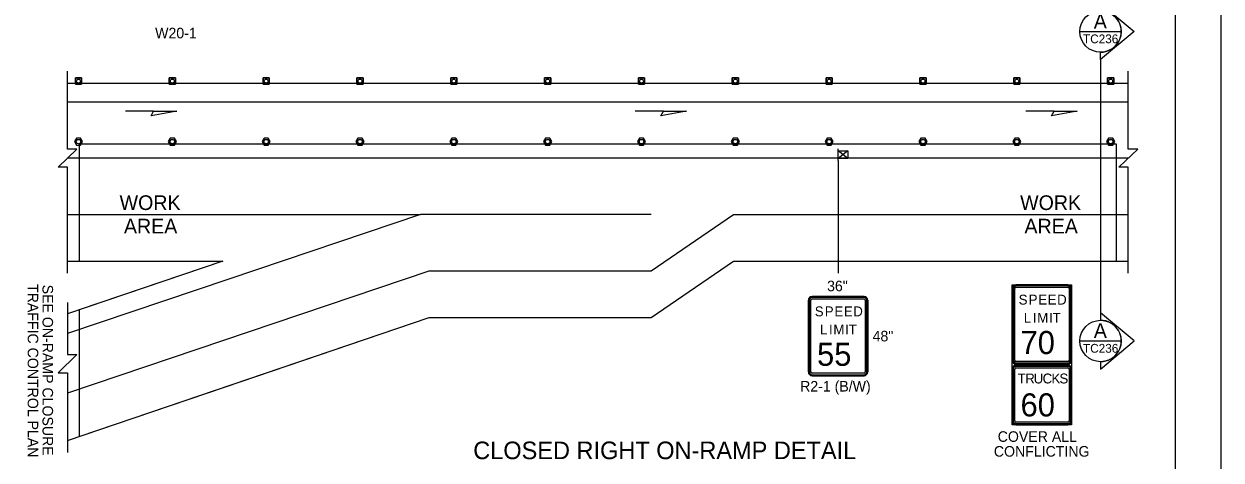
# Model space of a CAD drawing. Extents: x 99999 to 100116, y 99995 to 100013.
# Drawn here: x 100067.9 to 100076.06, y 100001.79 to 100004.77 of the extents above; entities that cross this region are included whole.
import ezdxf

# ---------------------------------------------------------------- set-up
doc = ezdxf.new("R2010")
doc.units = 0
for name, color, linetype in [('Default', 7, 'Continuous'), ('RD_MK_LineEdgeYellow', 7, 'Continuous'), ('RD_MK_LineLane', 7, 'Continuous'), ('SH_DE_DetailHeading2Text', 7, 'Continuous'), ('SH_GI_PlotLimits', 7, 'Continuous'), ('SH_GI_SheetBorder', 7, 'Continuous'), ('SH_TI_WZSectionCut', 7, 'Continuous'), ('TR_SN_ConstructionSigns', 7, 'Continuous'), ('TR_WZ_PortableSignMount5ftMinBlk-Wht', 7, 'Continuous'), ('TR_WZ_TallChanDevice', 7, 'Continuous'), ('TR_WZ_TrafficCone', 7, 'Continuous'), ('TR_WZ_WorkAreaLabel', 7, 'Continuous'), ('TR_WZ_WorkZoneDetails', 7, 'Continuous')]:
    doc.layers.add(name, color=color, linetype=linetype)

msp = doc.modelspace()

# ---------------------------------------------------------------- linework, layer by layer
at = {"layer": 'Default'}
for p, q in [((100074.638, 100002.4156), (100074.638, 100002.0613)), ((100075.0177, 100002.441), (100074.6633, 100002.441)), ((100075.043, 100002.0613), (100075.043, 100002.4156)), ((100074.6633, 100002.036), (100075.0177, 100002.036))]:
    msp.add_line(p, q, dxfattribs=at)
for centre, start, end in [((100074.6633, 100002.4156), 90, 180), ((100075.0177, 100002.4156), 0, 90), ((100074.6633, 100002.0613), 180, 270.00001), ((100075.0177, 100002.0613), 270.00001, 0.00001)]:
    msp.add_arc(centre, 0.0253, start, end, dxfattribs=at)
at = {"layer": 'RD_MK_LineEdgeYellow'}
for p, q in [((100068.195, 100004.238), (100075.43, 100004.238)), ((100068.195, 100003.47), (100069.2533, 100003.47)), ((100072.1758, 100003.086), (100072.7368, 100003.47)), ((100072.7368, 100003.47), (100075.43, 100003.47)), ((100070.6655, 100003.086), (100068.195, 100002.2517)), ((100070.6655, 100003.086), (100072.1758, 100003.086)), ((100069.2943, 100003.0282), (100068.195, 100002.657))]:
    msp.add_line(p, q, dxfattribs=at)
at = {"layer": 'RD_MK_LineLane'}
for points in [[(100075.43, 100003.854), (100068.195, 100003.854)], [(100072.1758, 100003.47), (100070.6024, 100003.47)]]:
    msp.add_lwpolyline(points, dxfattribs=at)
at = {"layer": 'SH_GI_PlotLimits'}
msp.add_lwpolyline([(100059.0625, 99999.6875), (100076.0625, 99999.6875), (100076.0625, 100010.6875), (100059.0625, 100010.6875)], close=True, dxfattribs=at)
at = {"layer": 'SH_GI_SheetBorder'}
msp.add_line((100075.75, 100010.375), (100075.75, 100000), dxfattribs=at)
at = {"layer": 'SH_TI_WZSectionCut'}
for p, q in [((100075.2407, 100004.9082), (100075.4688, 100004.7171)), ((100075.4688, 100004.7171), (100075.2407, 100004.526)), ((100075.2407, 100004.526), (100075.2407, 100004.5759)), ((100075.2407, 100004.526), (100075.2407, 100002.798)), ((100075.2407, 100002.798), (100075.2407, 100002.748)), ((100075.4689, 100002.6068), (100075.2407, 100002.798)), ((100075.2407, 100002.4157), (100075.4689, 100002.6068)), ((100075.2407, 100002.4656), (100075.2407, 100002.4157))]:
    msp.add_line(p, q, dxfattribs=at)
for points in [[(100075.0995, 100004.7171), (100075.3819, 100004.7171)], [(100075.0995, 100002.6068), (100075.3819, 100002.6068)]]:
    msp.add_lwpolyline(points, dxfattribs=at)
for centre in [(100075.2407, 100004.7171), (100075.2407, 100002.6068)]:
    msp.add_circle(centre, 0.1412, dxfattribs=at)
for centre in [(100075.2407, 100004.7171), (100075.2407, 100002.6068)]:
    msp.add_arc(centre, 0.1412, 269.99779, 90.00221, dxfattribs=at)
at = {"layer": 'TR_SN_ConstructionSigns'}
for p, q in [((100074.638, 100002.4753), (100074.638, 100002.9646)), ((100074.638, 100002.9646), (100074.638, 100002.4753)), ((100074.6451, 100002.9646), (100074.6451, 100002.4753)), ((100074.6549, 100002.4753), (100074.6549, 100002.9646)), ((100074.6633, 100002.99), (100075.0177, 100002.99)), ((100075.0177, 100002.99), (100074.6633, 100002.99)), ((100075.0177, 100002.9829), (100074.6633, 100002.9829)), ((100074.6633, 100002.9731), (100075.0177, 100002.9731)), ((100075.0261, 100002.9646), (100075.0261, 100002.4753)), ((100075.036, 100002.4753), (100075.036, 100002.9646)), ((100075.043, 100002.9646), (100075.043, 100002.4753)), ((100075.043, 100002.4753), (100075.043, 100002.9646)), ((100073.2475, 100002.3953), (100073.2475, 100002.8846)), ((100073.2475, 100002.8846), (100073.2475, 100002.3953)), ((100073.2546, 100002.8846), (100073.2546, 100002.3953)), ((100073.2644, 100002.3953), (100073.2644, 100002.8846)), ((100073.2728, 100002.91), (100073.6272, 100002.91)), ((100073.6272, 100002.91), (100073.2728, 100002.91)), ((100073.6272, 100002.9029), (100073.2728, 100002.9029)), ((100073.2728, 100002.8931), (100073.6272, 100002.8931)), ((100073.6357, 100002.8846), (100073.6357, 100002.3953)), ((100073.6455, 100002.3953), (100073.6455, 100002.8846)), ((100073.6525, 100002.8846), (100073.6525, 100002.3953)), ((100073.6525, 100002.3953), (100073.6525, 100002.8846)), ((100075.0177, 100002.4668), (100074.6633, 100002.4668)), ((100073.6272, 100002.3868), (100073.2728, 100002.3868)), ((100073.2728, 100002.377), (100073.6272, 100002.377)), ((100074.638, 100002.0613), (100074.638, 100002.4156)), ((100074.638, 100002.4156), (100074.638, 100002.0613)), ((100074.6451, 100002.4156), (100074.6451, 100002.0613)), ((100074.6549, 100002.0613), (100074.6549, 100002.4156)), ((100074.6633, 100002.457), (100075.0177, 100002.457)), ((100075.0177, 100002.45), (100074.6633, 100002.45)), ((100074.6633, 100002.45), (100075.0177, 100002.45)), ((100074.6633, 100002.441), (100075.0177, 100002.441)), ((100075.0177, 100002.441), (100074.6633, 100002.441)), ((100075.0177, 100002.4339), (100074.6633, 100002.4339)), ((100074.6633, 100002.4241), (100075.0177, 100002.4241)), ((100075.0261, 100002.4156), (100075.0261, 100002.0613)), ((100075.036, 100002.0613), (100075.036, 100002.4156)), ((100075.043, 100002.4156), (100075.043, 100002.0613)), ((100075.043, 100002.0613), (100075.043, 100002.4156)), ((100073.6272, 100002.37), (100073.2728, 100002.37)), ((100073.2728, 100002.37), (100073.6272, 100002.37)), ((100075.0177, 100002.0528), (100074.6633, 100002.0528)), ((100074.6633, 100002.043), (100075.0177, 100002.043)), ((100075.0177, 100002.036), (100074.6633, 100002.036)), ((100074.6633, 100002.036), (100075.0177, 100002.036))]:
    msp.add_line(p, q, dxfattribs=at)
msp.add_lwpolyline([(100074.638, 100002.99), (100075.043, 100002.99), (100075.043, 100002.036), (100074.638, 100002.036)], close=True, dxfattribs=at)
for centre, radius, start, end in [((100074.6633, 100002.9646), 0.0253, 90, 180), ((100074.6633, 100002.9646), 0.0253, 90, 180), ((100074.6633, 100002.9646), 0.0183, 90, 180), ((100074.6633, 100002.9646), 0.00844, 90, 180), ((100075.0177, 100002.9646), 0.0253, 0, 90), ((100075.0177, 100002.9646), 0.0253, 360, 90), ((100075.0177, 100002.9646), 0.0183, 0, 90), ((100075.0177, 100002.9646), 0.00844, 360, 90), ((100073.2728, 100002.8846), 0.0253, 90, 180), ((100073.2728, 100002.8846), 0.0253, 90, 180), ((100073.2728, 100002.8846), 0.0183, 90, 180), ((100073.2728, 100002.8846), 0.00844, 90, 180), ((100073.6272, 100002.8846), 0.0253, 360, 90), ((100073.6272, 100002.8846), 0.0253, 360, 90), ((100073.6272, 100002.8846), 0.0183, 0, 90), ((100073.6272, 100002.8846), 0.00844, 360, 90), ((100074.6633, 100002.4753), 0.0253, 180, 270), ((100074.6633, 100002.4753), 0.0253, 180, 270), ((100074.6633, 100002.4753), 0.0183, 180, 270), ((100074.6633, 100002.4753), 0.00844, 180, 270), ((100075.0177, 100002.4753), 0.0253, 270, 0), ((100075.0177, 100002.4753), 0.0183, 270, 360), ((100075.0177, 100002.4753), 0.00844, 270, 0), ((100075.0177, 100002.4753), 0.0253, 270, 0), ((100073.2728, 100002.3953), 0.0253, 180, 270), ((100073.2728, 100002.3953), 0.0253, 180, 270), ((100073.2728, 100002.3953), 0.0183, 180, 270), ((100073.2728, 100002.3953), 0.00844, 180, 270), ((100073.6272, 100002.3953), 0.0253, 270, 360), ((100073.6272, 100002.3953), 0.0183, 270, 360), ((100073.6272, 100002.3953), 0.00844, 270, 0), ((100073.6272, 100002.3953), 0.0253, 270, 360), ((100074.6633, 100002.4156), 0.0253, 90, 180), ((100074.6633, 100002.4156), 0.0253, 90, 180), ((100074.6633, 100002.4156), 0.0183, 90, 180), ((100074.6633, 100002.4156), 0.00844, 90, 180), ((100075.0177, 100002.4156), 0.0253, 0, 90), ((100075.0177, 100002.4156), 0.0253, 360, 90), ((100075.0177, 100002.4156), 0.0183, 0, 90), ((100075.0177, 100002.4156), 0.00844, 360, 90), ((100074.6633, 100002.0613), 0.0253, 180, 270), ((100074.6633, 100002.0613), 0.0253, 180, 270), ((100075.0177, 100002.0613), 0.0253, 270, 0), ((100075.0177, 100002.0613), 0.0253, 270, 0), ((100075.0177, 100002.0613), 0.0183, 270, 360), ((100075.0177, 100002.0613), 0.00844, 270, 0)]:
    msp.add_arc(centre, radius, start, end, dxfattribs=at)
for major_axis, ratio, start_param, end_param in [((-0.0183, 0), 0.999596, 0, 1.570796), ((0.00844, 0), 0.99908, 3.141593, 4.712389)]:
    msp.add_ellipse((100074.6633, 100002.0613), major_axis=major_axis, ratio=ratio, start_param=start_param, end_param=end_param, dxfattribs=at)
at = {"layer": 'TR_WZ_PortableSignMount5ftMinBlk-Wht'}
for p, q in [((100073.45, 100003.838), (100073.45, 100003.918)), ((100073.5167, 100003.904), (100073.45, 100003.852)), ((100073.5167, 100003.852), (100073.45, 100003.904)), ((100073.4834, 100003.878), (100073.4834, 100003.878)), ((100073.4835, 100003.878), (100073.4835, 100003.878))]:
    msp.add_line(p, q, dxfattribs=at)
msp.add_lwpolyline([(100073.5167, 100003.904), (100073.5167, 100003.852), (100073.45, 100003.852), (100073.45, 100003.904)], close=True, dxfattribs=at)
at = {"layer": 'TR_WZ_TallChanDevice'}
for points in [[(100068.2833, 100003.9909), (100068.2555, 100003.9909), (100068.2417, 100003.9669), (100068.2555, 100003.9429), (100068.2833, 100003.9429), (100068.2971, 100003.9669)], [(100068.9233, 100003.9909), (100068.8955, 100003.9909), (100068.8817, 100003.9669), (100068.8955, 100003.9429), (100068.9233, 100003.9429), (100068.9371, 100003.9669)], [(100069.5633, 100003.9909), (100069.5355, 100003.9909), (100069.5217, 100003.9669), (100069.5355, 100003.9429), (100069.5633, 100003.9429), (100069.5771, 100003.9669)], [(100070.2033, 100003.9909), (100070.1755, 100003.9909), (100070.1617, 100003.9669), (100070.1755, 100003.9429), (100070.2033, 100003.9429), (100070.2171, 100003.9669)], [(100070.8433, 100003.9909), (100070.8155, 100003.9909), (100070.8017, 100003.9669), (100070.8155, 100003.9429), (100070.8433, 100003.9429), (100070.8571, 100003.9669)], [(100071.4833, 100003.9909), (100071.4555, 100003.9909), (100071.4417, 100003.9669), (100071.4555, 100003.9429), (100071.4833, 100003.9429), (100071.4971, 100003.9669)], [(100072.1233, 100003.9909), (100072.0955, 100003.9909), (100072.0817, 100003.9669), (100072.0955, 100003.9429), (100072.1233, 100003.9429), (100072.1371, 100003.9669)], [(100072.7633, 100003.9909), (100072.7355, 100003.9909), (100072.7217, 100003.9669), (100072.7355, 100003.9429), (100072.7633, 100003.9429), (100072.7771, 100003.9669)], [(100073.4033, 100003.9909), (100073.3755, 100003.9909), (100073.3617, 100003.9669), (100073.3755, 100003.9429), (100073.4033, 100003.9429), (100073.4171, 100003.9669)], [(100074.0433, 100003.9909), (100074.0155, 100003.9909), (100074.0017, 100003.9669), (100074.0155, 100003.9429), (100074.0433, 100003.9429), (100074.0571, 100003.9669)], [(100074.6833, 100003.9909), (100074.6555, 100003.9909), (100074.6417, 100003.9669), (100074.6555, 100003.9429), (100074.6833, 100003.9429), (100074.6971, 100003.9669)], [(100075.3233, 100003.9909), (100075.2955, 100003.9909), (100075.2817, 100003.9669), (100075.2955, 100003.9429), (100075.3233, 100003.9429), (100075.3371, 100003.9669)]]:
    msp.add_lwpolyline(points, close=True, dxfattribs=at)
for points in [[(100068.2833, 100003.9909), (100068.2555, 100003.9909), (100068.2417, 100003.9669), (100068.2555, 100003.9429), (100068.2833, 100003.9429), (100068.2971, 100003.9669), (100068.2833, 100003.9909)], [(100068.9233, 100003.9909), (100068.8955, 100003.9909), (100068.8817, 100003.9669), (100068.8955, 100003.9429), (100068.9233, 100003.9429), (100068.9371, 100003.9669), (100068.9233, 100003.9909)], [(100069.5633, 100003.9909), (100069.5355, 100003.9909), (100069.5217, 100003.9669), (100069.5355, 100003.9429), (100069.5633, 100003.9429), (100069.5771, 100003.9669), (100069.5633, 100003.9909)], [(100070.2033, 100003.9909), (100070.1755, 100003.9909), (100070.1617, 100003.9669), (100070.1755, 100003.9429), (100070.2033, 100003.9429), (100070.2171, 100003.9669), (100070.2033, 100003.9909)], [(100070.8433, 100003.9909), (100070.8155, 100003.9909), (100070.8017, 100003.9669), (100070.8155, 100003.9429), (100070.8433, 100003.9429), (100070.8571, 100003.9669), (100070.8433, 100003.9909)], [(100071.4833, 100003.9909), (100071.4555, 100003.9909), (100071.4417, 100003.9669), (100071.4555, 100003.9429), (100071.4833, 100003.9429), (100071.4971, 100003.9669), (100071.4833, 100003.9909)], [(100072.1233, 100003.9909), (100072.0955, 100003.9909), (100072.0817, 100003.9669), (100072.0955, 100003.9429), (100072.1233, 100003.9429), (100072.1371, 100003.9669), (100072.1233, 100003.9909)], [(100072.7633, 100003.9909), (100072.7355, 100003.9909), (100072.7217, 100003.9669), (100072.7355, 100003.9429), (100072.7633, 100003.9429), (100072.7771, 100003.9669), (100072.7633, 100003.9909)], [(100073.4033, 100003.9909), (100073.3755, 100003.9909), (100073.3617, 100003.9669), (100073.3755, 100003.9429), (100073.4033, 100003.9429), (100073.4171, 100003.9669), (100073.4033, 100003.9909)], [(100074.0433, 100003.9909), (100074.0155, 100003.9909), (100074.0017, 100003.9669), (100074.0155, 100003.9429), (100074.0433, 100003.9429), (100074.0571, 100003.9669), (100074.0433, 100003.9909)], [(100074.6833, 100003.9909), (100074.6555, 100003.9909), (100074.6417, 100003.9669), (100074.6555, 100003.9429), (100074.6833, 100003.9429), (100074.6971, 100003.9669), (100074.6833, 100003.9909)], [(100075.3233, 100003.9909), (100075.2955, 100003.9909), (100075.2817, 100003.9669), (100075.2955, 100003.9429), (100075.3233, 100003.9429), (100075.3371, 100003.9669), (100075.3233, 100003.9909)]]:
    msp.add_lwpolyline(points, dxfattribs=at)
for centre in [(100068.2694, 100003.9669), (100068.9094, 100003.9669), (100069.5494, 100003.9669), (100070.1894, 100003.9669), (100070.8294, 100003.9669), (100071.4694, 100003.9669), (100072.1094, 100003.9669), (100072.7494, 100003.9669), (100073.3894, 100003.9669), (100074.0294, 100003.9669), (100074.6694, 100003.9669), (100075.3094, 100003.9669)]:
    msp.add_circle(centre, 0.015, dxfattribs=at)
at = {"layer": 'TR_WZ_TrafficCone'}
for points in [[(100068.2481, 100004.4006), (100068.2907, 100004.4006), (100068.2907, 100004.358), (100068.2481, 100004.358), (100068.2481, 100004.4006)], [(100068.2481, 100004.358), (100068.2907, 100004.358), (100068.2907, 100004.4006), (100068.2481, 100004.4006), (100068.2481, 100004.358)], [(100068.8881, 100004.4006), (100068.9307, 100004.4006), (100068.9307, 100004.358), (100068.8881, 100004.358), (100068.8881, 100004.4006)], [(100068.8881, 100004.358), (100068.9307, 100004.358), (100068.9307, 100004.4006), (100068.8881, 100004.4006), (100068.8881, 100004.358)], [(100069.5281, 100004.4006), (100069.5707, 100004.4006), (100069.5707, 100004.358), (100069.5281, 100004.358), (100069.5281, 100004.4006)], [(100069.5281, 100004.358), (100069.5707, 100004.358), (100069.5707, 100004.4006), (100069.5281, 100004.4006), (100069.5281, 100004.358)], [(100070.1681, 100004.4006), (100070.2107, 100004.4006), (100070.2107, 100004.358), (100070.1681, 100004.358), (100070.1681, 100004.4006)], [(100070.1681, 100004.358), (100070.2107, 100004.358), (100070.2107, 100004.4006), (100070.1681, 100004.4006), (100070.1681, 100004.358)], [(100070.8081, 100004.4006), (100070.8507, 100004.4006), (100070.8507, 100004.358), (100070.8081, 100004.358), (100070.8081, 100004.4006)], [(100070.8081, 100004.358), (100070.8507, 100004.358), (100070.8507, 100004.4006), (100070.8081, 100004.4006), (100070.8081, 100004.358)], [(100071.4481, 100004.4006), (100071.4907, 100004.4006), (100071.4907, 100004.358), (100071.4481, 100004.358), (100071.4481, 100004.4006)], [(100071.4481, 100004.358), (100071.4907, 100004.358), (100071.4907, 100004.4006), (100071.4481, 100004.4006), (100071.4481, 100004.358)], [(100072.0881, 100004.4006), (100072.1307, 100004.4006), (100072.1307, 100004.358), (100072.0881, 100004.358), (100072.0881, 100004.4006)], [(100072.0881, 100004.358), (100072.1307, 100004.358), (100072.1307, 100004.4006), (100072.0881, 100004.4006), (100072.0881, 100004.358)], [(100072.7281, 100004.4006), (100072.7707, 100004.4006), (100072.7707, 100004.358), (100072.7281, 100004.358), (100072.7281, 100004.4006)], [(100072.7281, 100004.358), (100072.7707, 100004.358), (100072.7707, 100004.4006), (100072.7281, 100004.4006), (100072.7281, 100004.358)], [(100073.3681, 100004.4006), (100073.4107, 100004.4006), (100073.4107, 100004.358), (100073.3681, 100004.358), (100073.3681, 100004.4006)], [(100073.3681, 100004.358), (100073.4107, 100004.358), (100073.4107, 100004.4006), (100073.3681, 100004.4006), (100073.3681, 100004.358)], [(100074.0081, 100004.4006), (100074.0507, 100004.4006), (100074.0507, 100004.358), (100074.0081, 100004.358), (100074.0081, 100004.4006)], [(100074.0081, 100004.358), (100074.0507, 100004.358), (100074.0507, 100004.4006), (100074.0081, 100004.4006), (100074.0081, 100004.358)], [(100074.6481, 100004.4006), (100074.6907, 100004.4006), (100074.6907, 100004.358), (100074.6481, 100004.358), (100074.6481, 100004.4006)], [(100074.6481, 100004.358), (100074.6907, 100004.358), (100074.6907, 100004.4006), (100074.6481, 100004.4006), (100074.6481, 100004.358)], [(100075.2881, 100004.4006), (100075.3307, 100004.4006), (100075.3307, 100004.358), (100075.2881, 100004.358), (100075.2881, 100004.4006)], [(100075.2881, 100004.358), (100075.3307, 100004.358), (100075.3307, 100004.4006), (100075.2881, 100004.4006), (100075.2881, 100004.358)]]:
    msp.add_lwpolyline(points, dxfattribs=at)
for centre in [(100068.2694, 100004.3793), (100068.9094, 100004.3793), (100069.5494, 100004.3793), (100070.1894, 100004.3793), (100070.8294, 100004.3793), (100071.4694, 100004.3793), (100072.1094, 100004.3793), (100072.7494, 100004.3793), (100073.3894, 100004.3793), (100074.0294, 100004.3793), (100074.6694, 100004.3793), (100075.3094, 100004.3793)]:
    msp.add_circle(centre, 0.0133, dxfattribs=at)
at = {"layer": 'TR_WZ_WorkZoneDetails'}
for p, q in [((100068.195, 100004.366), (100075.43, 100004.366)), ((100068.782, 100004.174), (100068.5891, 100004.174)), ((100072.2594, 100004.174), (100072.0665, 100004.174)), ((100074.9242, 100004.174), (100074.7313, 100004.174)), ((100073.45, 100003.838), (100073.45, 100003.07)), ((100069.2533, 100003.47), (100070.6024, 100003.47)), ((100070.6024, 100003.47), (100069.2943, 100003.0282)), ((100068.195, 100003.15), (100069.2533, 100003.15)), ((100069.2533, 100003.15), (100068.195, 100002.7929)), ((100072.1758, 100002.766), (100072.7368, 100003.15)), ((100072.7368, 100003.15), (100075.43, 100003.15)), ((100068.195, 100001.928), (100070.6601, 100002.766)), ((100070.6601, 100002.766), (100072.1758, 100002.766))]:
    msp.add_line(p, q, dxfattribs=at)
for points in [[(100068.195, 100003.07), (100068.195, 100003.792), (100068.131, 100003.792), (100068.259, 100003.9159), (100068.195, 100003.9159), (100068.195, 100004.446)], [(100075.43, 100003.07), (100075.43, 100003.792), (100075.366, 100003.792), (100075.494, 100003.9159), (100075.43, 100003.9159), (100075.43, 100004.446)], [(100068.195, 100002.8701), (100068.195, 100002.5136), (100068.259, 100002.5136), (100068.131, 100002.3897), (100068.195, 100002.3897), (100068.195, 100001.8453)]]:
    msp.add_lwpolyline(points, dxfattribs=at)
for points in [[(100068.9392, 100004.174), (100068.7641, 100004.1431), (100068.782, 100004.174)], [(100072.4166, 100004.174), (100072.2415, 100004.1431), (100072.2594, 100004.174)], [(100075.0815, 100004.174), (100074.9064, 100004.1431), (100074.9242, 100004.174)], [(100068.275, 100003.95), (100068.275, 100003.15), (100069.2533, 100003.15), (100068.275, 100002.8199), (100068.275, 100002.8199), (100068.275, 100002.8199), (100068.275, 100001.9552), (100068.275, 100001.9552), (100068.275, 100001.9552), (100069.2728, 100002.2944), (100070.6601, 100002.766), (100072.1758, 100002.766), (100072.7368, 100003.15), (100075.35, 100003.15), (100075.35, 100003.95)]]:
    msp.add_lwpolyline(points, close=True, dxfattribs=at)

# ---------------------------------------------------------------- texts
at = {"layer": 'Default'}
for s, height, p in [('S', 0.0675, (100074.6819, 100002.855)), ('P', 0.0675, (100074.7501, 100002.855)), ('E', 0.0675, (100074.8162, 100002.855)), ('E', 0.0675, (100074.8803, 100002.855)), ('D', 0.0675, (100074.9445, 100002.855)), ('S', 0.0675, (100073.2914, 100002.775)), ('P', 0.0675, (100073.3596, 100002.775)), ('E', 0.0675, (100073.4257, 100002.775)), ('E', 0.0675, (100073.4899, 100002.775)), ('D', 0.0675, (100073.554, 100002.775)), ('L', 0.0675, (100074.717, 100002.7312)), ('I', 0.0675, (100074.7791, 100002.7312)), ('M', 0.0675, (100074.8088, 100002.7312)), ('I', 0.0675, (100074.8898, 100002.7312)), ('T', 0.0675, (100074.9134, 100002.7312)), ('L', 0.0675, (100073.3265, 100002.6512)), ('I', 0.0675, (100073.3886, 100002.6512)), ('M', 0.0675, (100073.4183, 100002.6512)), ('I', 0.0675, (100073.4993, 100002.6512)), ('T', 0.0675, (100073.5229, 100002.6512)), ('70', 0.1575, (100074.6949, 100002.5175)), ('55', 0.1575, (100073.3068, 100002.4375)), ('T', 0.0675, (100074.6751, 100002.3172)), ('R', 0.0675, (100074.7271, 100002.3172)), ('U', 0.0675, (100074.7845, 100002.3172)), ('C', 0.0675, (100074.8452, 100002.3172)), ('K', 0.0675, (100074.906, 100002.3172)), ('S', 0.0675, (100074.96, 100002.3172)), ('60', 0.1575, (100074.6948, 100002.0922))]:
    msp.add_text(s, height=height, dxfattribs=at).set_placement(p)
at = {"layer": 'SH_DE_DetailHeading2Text'}
msp.add_text('CLOSED RIGHT ON-RAMP DETAIL', height=0.12, rotation=360, dxfattribs=at).set_placement((100070.9618, 100001.8009))
at = {"layer": 'SH_TI_WZSectionCut'}
for s, height, rotation, p in [('A', 0.1, 0.00995, (100075.1945, 100004.7377)), ('TC236', 0.06, 360, (100075.1209, 100004.6371)), ('A', 0.1, 0.00995, (100075.1945, 100002.6275)), ('TC236', 0.06, 360, (100075.1209, 100002.5268))]:
    msp.add_text(s, height=height, rotation=rotation, dxfattribs=at).set_placement(p)
at = {"layer": 'TR_SN_ConstructionSigns'}
msp.add_text('W20-1', height=0.072, rotation=360, dxfattribs=at).set_placement((100068.7921, 100004.6705))
for s, p in [('36"', (100073.3753, 100002.946)), ('COVER ALL', (100074.5392, 100001.919)), ('CONFLICTING', (100074.5128, 100001.8182))]:
    msp.add_text(s, height=0.072, dxfattribs=at).set_placement(p)
at = {"layer": 'TR_WZ_WorkAreaLabel'}
for s, p in [('WORK', (100068.5496, 100003.5)), ('WORK', (100074.6919, 100003.5)), ('AREA', (100068.5793, 100003.34)), ('AREA', (100074.7215, 100003.34))]:
    msp.add_text(s, height=0.1, dxfattribs=at).set_placement(p)
at = {"layer": 'TR_WZ_WorkZoneDetails'}
for s, p in [('TRAFFIC CONTROL PLAN', (100067.923, 100002.9948)), ('SEE ON-RAMP CLOSURE', (100068.0238, 100002.9908))]:
    msp.add_text(s, height=0.072, rotation=270, dxfattribs=at).set_placement(p)
for s, p in [('48"', (100073.6858, 100002.604)), ('R2-1 (B/W)', (100073.1913, 100002.262))]:
    msp.add_text(s, height=0.072, dxfattribs=at).set_placement(p)

doc.saveas('drawing.dxf')
